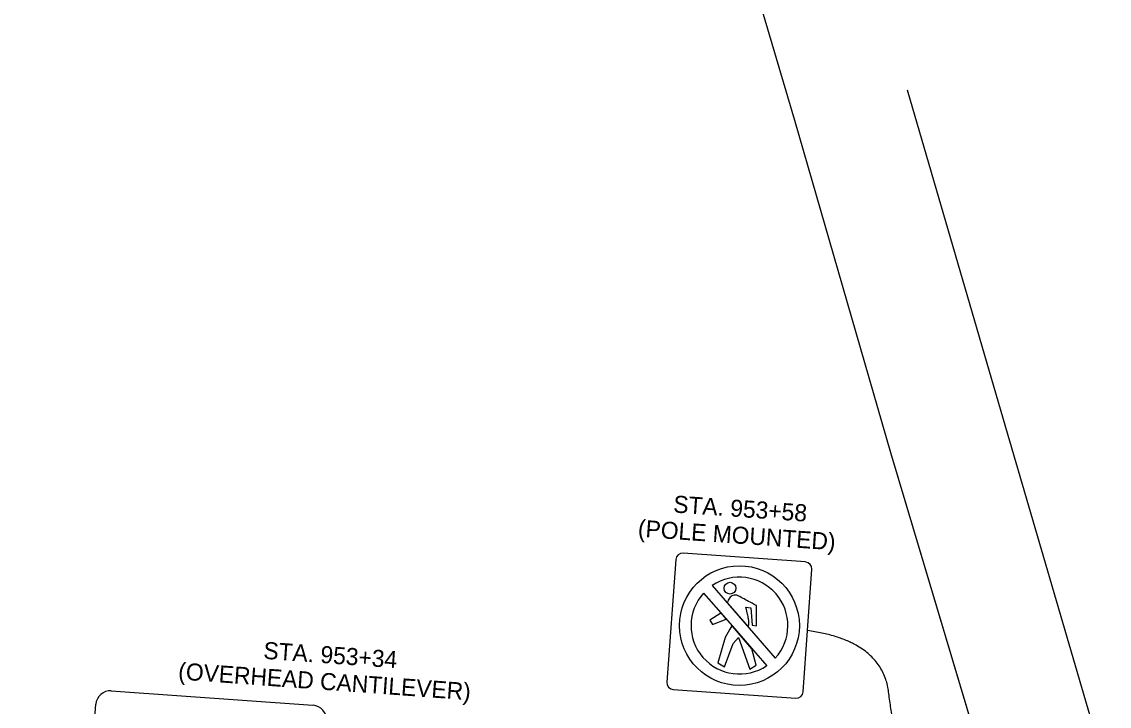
# Model space of a CAD drawing. Extents: x 1847379 to 1850904, y 217032 to 220169.
# Drawn here: x 1849366.2 to 1849525.4, y 218960 to 219060.2 of the extents above; entities that cross this region are included whole.
import ezdxf

# ---------------------------------------------------------------- set-up
doc = ezdxf.new("R2010")
doc.units = 0
for name, color, linetype in [('BR_P_Gen_Approach_Slab_Hidden', 7, 'Continuous'), ('SN_X_Public', 7, 'Continuous'), ('SN_X_Text', 7, 'Continuous')]:
    doc.layers.add(name, color=color, linetype=linetype)

msp = doc.modelspace()

# ---------------------------------------------------------------- linework, layer by layer
at = {"layer": 'BR_P_Gen_Approach_Slab_Hidden'}
for p, q in [((1849509.86, 219002.01), (1849495.81, 219050.24)), ((1849493.36, 218997.12), (1849479.33, 219045.76)), ((1849525.36, 218948.96), (1849509.86, 219002.01)), ((1849508.93, 218944.96), (1849493.36, 218997.12))]:
    msp.add_line(p, q, dxfattribs=at)
msp.add_lwpolyline([(1849366.15, 218857.41), (1849433.63, 218853.3), (1849498.54, 218849.15), (1849498.58, 218849.37), (1849508.29, 218861.54), (1849514.81, 218874.18), (1849518.45, 218897.75), (1849514.45, 218923.71), (1849508.93, 218944.96), (1849493.36, 218997.12), (1849479.33, 219045.76), (1849461.72, 219105.45), (1849446.36, 219158.7), (1849432.03, 219205.83)], dxfattribs=at)
at = {"layer": 'SN_X_Public'}
for p, q in [((1849467.25, 218977.67), (1849476.47, 218967.02)), ((1849469.42, 218975.16), (1849469.52, 218975.05)), ((1849469.52, 218975.05), (1849472.5, 218971.61)), ((1849472.17, 218974.49), (1849472.9, 218974.41)), ((1849472.17, 218974.49), (1849472.9, 218974.41)), ((1849472.9, 218974.41), (1849473.09, 218971.85)), ((1849472.9, 218974.41), (1849473.09, 218971.85)), ((1849473.71, 218974.75), (1849473.69, 218974.75)), ((1849473.71, 218974.75), (1849473.69, 218974.75)), ((1849473.72, 218971.75), (1849473.71, 218974.75)), ((1849473.72, 218971.75), (1849473.71, 218974.75)), ((1849468.51, 218973.64), (1849466.89, 218972.59)), ((1849468.51, 218973.64), (1849466.89, 218972.59)), ((1849466.89, 218972.59), (1849467.26, 218971.98)), ((1849466.89, 218972.59), (1849467.26, 218971.98)), ((1849467.26, 218971.98), (1849469.28, 218972.75)), ((1849467.26, 218971.98), (1849469.28, 218972.75)), ((1849469.28, 218972.75), (1849469.12, 218972.93)), ((1849469.83, 218971.28), (1849469.14, 218970.04)), ((1849469.83, 218971.28), (1849469.14, 218970.04)), ((1849470.13, 218971.77), (1849469.83, 218971.28)), ((1849470.13, 218971.77), (1849469.83, 218971.28)), ((1849470.19, 218971.71), (1849470.13, 218971.77)), ((1849473.05, 218968.41), (1849470.19, 218971.71)), ((1849473.09, 218971.85), (1849473.72, 218971.75)), ((1849473.09, 218971.85), (1849473.72, 218971.75)), ((1849469.14, 218970.04), (1849468.04, 218966.34)), ((1849469.14, 218970.04), (1849468.04, 218966.34)), ((1849469.03, 218965.75), (1849470.32, 218969.2)), ((1849469.03, 218965.75), (1849470.32, 218969.2)), ((1849470.32, 218969.2), (1849471.1, 218970.05)), ((1849470.32, 218969.2), (1849471.1, 218970.05)), ((1849471.1, 218970.05), (1849472.74, 218965.41)), ((1849471.1, 218970.05), (1849472.74, 218965.41)), ((1849473.68, 218966.01), (1849473.05, 218968.41)), ((1849473.68, 218966.01), (1849473.05, 218968.41)), ((1849468.04, 218966.34), (1849469.03, 218965.75)), ((1849468.04, 218966.34), (1849469.03, 218965.75)), ((1849472.74, 218965.41), (1849473.68, 218966.01)), ((1849472.74, 218965.41), (1849473.68, 218966.01))]:
    msp.add_line(p, q, dxfattribs=at)
for points in [[(1849480.91, 218981.12), (1849462.96, 218982.4)], [(1849461.89, 218981.47), (1849460.61, 218963.52)], [(1849480.56, 218962.09), (1849481.84, 218980.05)], [(1849465.97, 218976.56), (1849468.48, 218973.67), (1849469.13, 218972.94), (1849469.12, 218972.93)], [(1849469.52, 218975.05), (1849469.52, 218975.05)], [(1849469.12, 218972.93), (1849468.51, 218973.64), (1849468.51, 218973.64)], [(1849469.12, 218972.93), (1849470.19, 218971.71), (1849473.62, 218967.75), (1849475.21, 218965.93)], [(1849379.26, 218962.24), (1849408.79, 218960.14)], [(1849461.54, 218962.45), (1849479.49, 218961.17)], [(1849372.96, 218903.74), (1849377, 218960.28)]]:
    msp.add_lwpolyline(points, dxfattribs=at)
for centre, radius in [((1849471.22, 218971.8), 8.77), ((1849469.84, 218977.28), 0.864)]:
    msp.add_circle(centre, radius, dxfattribs=at)
for centre, radius, start, end in [((1849462.89, 218981.4), 1, 85.9213, 175.9213), ((1849480.84, 218980.12), 1, 355.9213, 85.9213), ((1849471.22, 218971.8), 7.09, 317.7404, 124.0927), ((1849471.22, 218971.8), 7.09, 137.7693, 304.1693), ((1849471.22, 218971.8), 7.09, 137.7693, 304.1693), ((1849461.61, 218963.45), 1, 175.9213, 265.9213), ((1849379.11, 218960.13), 2.12, 85.9213, 175.9213), ((1849479.56, 218962.17), 1, 265.9213, 355.9213), ((1849408.64, 218958.03), 2.12, 355.9213, 85.9213)]:
    msp.add_arc(centre, radius, start, end, dxfattribs=at)
for points, degree in [([(1849473.69, 218974.75), (1849472.84, 218975.2), (1849471.49, 218975.93), (1849471, 218976.2), (1849470.84, 218976.25), (1849470.67, 218976.26), (1849470.27, 218976.29), (1849469.73, 218975.85), (1849469.54, 218975.42), (1849469.42, 218975.16)], 3), ([(1849473.69, 218974.75), (1849472.84, 218975.2), (1849471.49, 218975.93), (1849471, 218976.2), (1849470.84, 218976.25), (1849470.67, 218976.26), (1849470.27, 218976.29), (1849469.73, 218975.85), (1849469.54, 218975.42), (1849469.42, 218975.16)], 3), ([(1849472.5, 218971.61), (1849472.54, 218971.68), (1849472.62, 218971.88), (1849472.61, 218972.34), (1849472.56, 218972.76), (1849472.41, 218973.49), (1849472.3, 218974), (1849472.17, 218974.49)], 3), ([(1849472.5, 218971.61), (1849472.54, 218971.68), (1849472.62, 218971.88), (1849472.61, 218972.34), (1849472.56, 218972.76), (1849472.41, 218973.49), (1849472.3, 218974), (1849472.17, 218974.49)], 3), ([(1849496.87, 218870.49), (1849502.46, 218883.6), (1849501.17, 218926.43), (1849493.99, 218954.23), (1849492.19, 218969.57), (1849481.2, 218971.07)], 2)]:
    msp.add_open_spline(points, degree=degree, dxfattribs=at)

# ---------------------------------------------------------------- texts
for s, p in [('STA. 953+34', (1849401.47, 218966.95)), ('(OVERHEAD CANTILEVER)', (1849389, 218963.92))]:
    msp.add_text(s, height=2.5, rotation=355.9213, dxfattribs=at).set_placement(p)
at = {"layer": 'SN_X_Text'}
for s, p in [('STA. 953+58', (1849461.47, 218988.38)), ('(POLE MOUNTED)', (1849456.3, 218984.83))]:
    msp.add_text(s, height=2.5, rotation=356.0293, dxfattribs=at).set_placement(p)

doc.saveas('drawing.dxf')
